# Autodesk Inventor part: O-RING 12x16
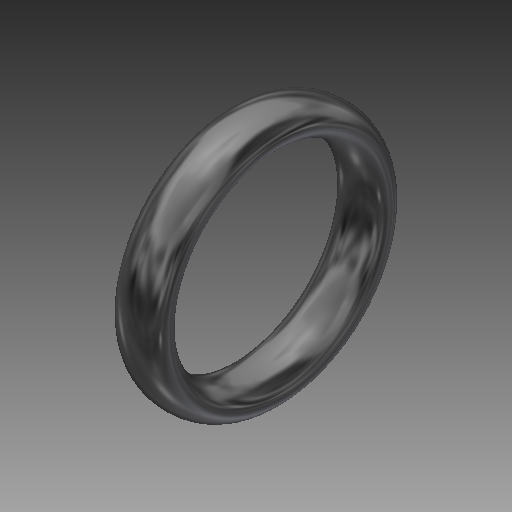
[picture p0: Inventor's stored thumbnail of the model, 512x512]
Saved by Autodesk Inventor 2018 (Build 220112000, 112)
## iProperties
Created: 2020-02
Part Number: O-RING 12x16
Material: 고무
Document SubType Name: Modeling
Designer: mduedu
Density: 1 g/cm^3
Appearance: 고무 - 검은색 - 버전 1.1
Author: mduedu
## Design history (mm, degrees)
sketch "스케치1"
  geometry: L1 (-2.24, 0)-(2.24, 0) reference; L2 (-1.6, 7)-(1.6, 7); L3 (0, 8)-(0, 6); 6 further points; 1 other entity
  constraints: 4 end point, 3 coincident, 2 midpoint, 1 horizontal, 1 vertical, 1 vertical alignment, 6 other
  dimensions: "d0" = 1.6 distance of point (1.6, 7) point (0, 7); "d2" = 12 diameter of point (0, 6) L1; "d3" = 16 diameter of point (0, 8) L1
revolve "회전1" sketch "스케치1" stored, may be unused: angle "d4" = 90 deg
node "솔리드1"
